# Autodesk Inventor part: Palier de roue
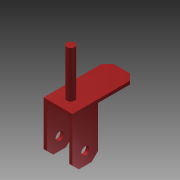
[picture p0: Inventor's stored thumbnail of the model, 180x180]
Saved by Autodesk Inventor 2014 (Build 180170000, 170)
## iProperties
Created: 2015-09
Part Number: Palier de roue
Material: Générique
Document SubType Name: Modeling
Designer: OL
Mass: 446.218 g
Surface Area: 994.926 cm^2
Volume: 446.218 cm^3
Density: 1 g/cm^3
Appearance: Par défaut
Author: OL
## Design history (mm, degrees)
sketch "Esquisse1"
  geometry: L1 (-20, -40)-(20, -40); L2 (40, -20)-(40, 110); L3 (-40, 7.431)-(-40, -20); L4 (40, 110)-(160, 110); L5 (160, 110)-(160, 120); L6 (160, 120)-(-40, 120); L7 (-40, 120)-(-40, 7.431); L8 (-40, -20)-(-20, -40); C1 r 0.692 at (0, 0); C2 r 12.5 at (0, 0); 1 further point; 1 other entity
  constraints: 16 end point, 3 parallel, 2 centre point, 2 coincident, 2 horizontal, 2 perpendicular, 4 other
  dimensions: "d0" = 40 distance from line of L2 point (0, 0); "d1" = 80 distance between parallel lines of L2 L3; "d2" = 20 horizontal distance of L3.end L1.start; "d3" = 20 horizontal distance of L3.end L1.start; "d4" = 20 horizontal distance of L1.end L2.start; "d5" = 10 distance between parallel lines of L6 L4; "d6" = 200 distance of L5.end L6.end; "d7" = 150 distance from line of L1 L2.end; "d8" = 40 distance from line of point (0, 0) L1; "d9" = 25 diameter of C2
extrude "Extrusion1" new body sketch "Esquisse1" distance "d10" = 90; taper "d11" = 0 deg
chamfer "Chanfrein1" distance "d12" = 20; stored, may be unused: second distance "d13" = 2, angle "d14" = 45 deg
sketch "Esquisse2"
  geometry: L1 (0, 0)-(0, 130) reference; L2 (0, 0)-(90, 0) reference; L3 (90, 130)-(90, 0) reference; L4 (10, 0)-(80, 0); L5 (80, 0)-(80, 173.03); L6 (80, 173.03)-(10, 173.03); L7 (10, 173.03)-(10, 0); 1 further point
  constraints: 8 end point, 2 parallel, 1 horizontal, 1 perpendicular, 1 point on line
  dimensions: "d15" = 10 distance between parallel lines of L1 L7; "d16" = 10 distance between parallel lines of L3 L5
extrude "Extrusion2" cut sketch "Esquisse2" distance "d17" = 80; taper "d18" = 0 deg
sketch "Esquisse3"
  geometry: L1 (90, 180)-(90, 0) reference; L2 (20, 200)-(70, 200) reference; C1 r 10 at (45, 170); 1 further point
  constraints: 1 centre point
  dimensions: "d19" = 30 distance from line of L2 C1.centre; "d20" = 20 diameter of C1; "d21" = 45 distance from line of L1 C1.centre
extrude "Extrusion3" join sketch "Esquisse3" distance "d22" = 33; taper "d23" = 0 deg
sketch "Esquisse4"
  geometry: L1 (0, 0)-(90, 0) reference; L2 (0, 0)-(0, 180) reference; C1 r 12.5 at (45, 40); 1 further point
  constraints: 1 centre point
  dimensions: "d24" = 25 diameter of C1; "d26" = 40 distance from line of L1 C1.centre; "d29" = 45 distance from line of L2 C1.centre
extrude "Extrusion4" join sketch "Esquisse4" distance "d27" = 145; taper "d28" = 0 deg
sketch "Esquisse5"
  geometry: L1 (0, 10)-(50, 10) reference; L2 (35, 33)-(15, 33) reference; C1 r 2.5 at (25, 25.5); 1 further point
  constraints: 1 centre point
  dimensions: "d30" = 5 diameter of C1; "d32" = 10 horizontal distance of L2.start C1.centre; "d33" = 15.5 distance from line of L1 C1.centre
extrude "Extrusion5" cut sketch "Esquisse5" distance "d34" = 30; taper "d35" = 0 deg
chamfer "Chanfrein2" distance "d36" = 1; stored, may be unused: second distance "d37" = 2, angle "d38" = 45 deg
node "Solide1"
